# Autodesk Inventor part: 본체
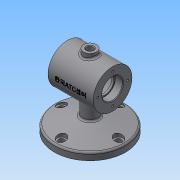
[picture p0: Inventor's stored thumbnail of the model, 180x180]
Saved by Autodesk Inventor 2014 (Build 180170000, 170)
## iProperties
Created: 2018-12
Part Number: 본체
Material: 일반
Document SubType Name: Modeling
Designer: net
Density: 1 g/cm^3
Appearance: 기본값
Mass: 253.122 g
Surface Area: 554.262 cm^2
Volume: 253.122 cm^3
Author: net
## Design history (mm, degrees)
sketch "스케치1"
  geometry: L1 (-35, 0)-(35, 0); L2 (-35, 0)-(-35, 30); L3 (-35, 30)-(35, 30); L4 (35, 30)-(35, 0); L5 (-35, 16)-(-23.3, 16); L6 (-23, 15.7)-(-23, 14); L7 (-23, 14)-(-20, 14); L8 (-20, 14)-(-20, 22); L9 (-17, 25)-(17, 25); L10 (20, 22)-(20, 14); L11 (20, 14)-(23, 14); L12 (23, 14)-(23, 15.7); L13 (23.3, 16)-(35, 16); A1 r 0.3 centre (-23.3, 15.7) between (-23, 15.7) and (-23.3, 16); A2 r 0.3 centre (23.3, 15.7) between (23.3, 16) and (23, 15.7); A3 r 3 centre (17, 22) between (20, 22) and (17, 25); A4 r 3 centre (-17, 22) between (-17, 25) and (-20, 22); 6 further points
  constraints: 26 end point, 10 point on line, 8 point on circle, 8 tangent, 7 parallel, 5 perpendicular, 4 centre point, 2 equal radius, 1 coincident, 1 horizontal, 1 midpoint
  dimensions: "d0" = 70 distance of L1.start L1.end; "d1" = 60 diameter of L3 L1; "d2" = 28 diameter of L7 L1; "d3" = 28 diameter of L11 L1; "d4" = 32 diameter of L5 L1; "d5" = 32 diameter of L13 L1; "d6" = 50 diameter of L9 L1; "d7" = 12 distance of L5.start point (-23, 16); "d8" = 12 distance of point (23, 16) L13.end; "d9" = 40 distance of point (-20, 25) point (20, 25); "d10" = 3 distance of L6.end L7.end; "d11" = 0.3 radius of A1; "d12" = 3 radius of A3
revolve "회전1" sketch "스케치1" stored, may be unused: angle "d13" = 90 deg
sketch "스케치2" dims "d14" = 46
  geometry: C1 r 16 at (0, 0) reference; 2 further points
  constraints: 2 vertical alignment, 1 coincident, 2 other
hole "구멍1" sketch "스케치2" at (0, 23) diameter "d15" = 3.242; stored, may be unused: countersink angle "d19" = 90 deg, drill point angle "d21" = 118 deg; dims "d16" = 8, "d17" = 4, "d18" = 2, "d20" = 10
chamfer "모따기1" distance "d25" = 1; stored, may be unused: second distance "d26" = 2, angle "d27" = 45 deg
node "작업 평면1"
sketch "스케치3"
  geometry: C1 r 55 at (0, 0); 1 further point
  constraints: 1 centre point, 1 coincident
  dimensions: "d29" = 110 diameter of C1
extrude "돌출1" join sketch "스케치3" distance "d30" = 11; taper "d31" = 0 deg
sketch "스케치4"
  geometry: L1 (-75, -55)-(-75, 55) reference; L2 (30, 0)-(-75, 0); L3 (-75, 55)-(-64, 55) reference; L4 (-64, 55)-(-64, -55) reference; L5 (-64, -55)-(-75, -55) reference; L6 (-64, 55)-(-52.478, 12); L7 (-52.478, 12)-(-64, 12); L8 (-64, 55)-(-64, 12); C1 r 25 at (0, 0) reference; 3 further points
  constraints: 8 end point, 2 horizontal alignment, 2 midpoint, 1 collinear, 1 perpendicular, 1 point on line, 1 other
  dimensions: "d39" = 75 deg angle of L6 L3; "d40" = 24 diameter of L6.end L2
revolve "회전2" sketch "스케치4" stored, may be unused: angle "d41" = 90 deg
fillet "모깎기2" dims "d42" = 3
sketch "스케치5"
  geometry: C1 r 12 at (0, 0) reference; C2 r 12 at (0, 0)
  constraints: 1 centre point, 1 coincident, 1 concentric
extrude "돌출2" join sketch "스케치5" stored distance "d43" = 1; taper "d44" = 0 deg
fillet "모깎기3" dims "d45" = 3
node "작업 평면2"
sketch "스케치6"
  geometry: C1 r 10 at (0, 0); 1 further point
  constraints: 1 centre point, 1 coincident
  dimensions: "d47" = 20 diameter of C1
extrude "돌출3" join sketch "스케치6" stored distance "d48" = 1; taper "d49" = 0 deg
sketch "스케치7"
  geometry: C1 r 10 at (0, 0) reference; C2 r 5 at (0, 0)
  constraints: 1 centre point, 1 coincident
  dimensions: "d50" = 10 diameter of C2
extrude "돌출4" cut sketch "스케치7" distance "d51" = 45; taper "d52" = 0 deg
fillet "모깎기4" dims "d53" = 3
sketch "스케치9" dims "d62" = 88
  geometry: C1 r 55 at (0, 0) reference; C2 r 4.5 at (0, 44); 1 further point
  constraints: 2 vertical alignment, 1 centre point, 1 coincident, 2 other
  dimensions: "d63" = 9 diameter of C2
extrude "돌출5" cut sketch "스케치9" stored distance "d64" = 10; taper "d65" = 0 deg
node "작업 평면3"
sketch "스케치11"
  geometry: C1 r 4.5 at (0, 44) reference; C2 r 54.703 at (0, 0) reference; C3 r 7 at (0, 44); 1 further point
  constraints: 1 centre point, 1 coincident
  dimensions: "d68" = 14 diameter of C3
extrude "돌출6" cut sketch "스케치11" distance "d69" = 15; taper "d70" = 0 deg
node "작업 평면4"
sketch "스케치12"
  geometry: L1 (35, -30)-(35, 30) reference; L2 (-35, 0)-(35, 0) reference; L3 (46.098, -75)-(-46.098, -75) reference; L4 (-46.098, -75)-(-46.098, -66.302) reference; L5 (46.098, -66.302)-(46.098, -75) reference; 4 further points
  constraints: 2 horizontal alignment, 3 other
  dimensions: "d74" = 35 distance from line of L1 point (0, 0)
feature "엠보싱1" sketch "스케치12" dims "d0" = 70, "d1" = 60, "d2" = 28, "d3" = 28, "d4" = 32, "d5" = 32, "d6" = 50, "d7" = 12, "d8" = 12, "d9" = 40, "d10" = 3, "d11" = 0.3, "d12" = 3, "d75" = 0.5, "d76" = 0
chamfer "모따기2" distance "d77" = 1; stored, may be unused: second distance "d78" = 2, angle "d79" = 45 deg
node "솔리드1"
pattern_circular "원형 패턴1" dims angle "d23" = 360 deg
mirror "대칭1"
pattern_circular "원형 패턴2" dims angle "d72" = 360 deg
node "절단 모서리 투영1"
node "절단 모서리 투영2"
node "절단 모서리 투영3"
other parameters: "d28" = -75, "d46" = 112
